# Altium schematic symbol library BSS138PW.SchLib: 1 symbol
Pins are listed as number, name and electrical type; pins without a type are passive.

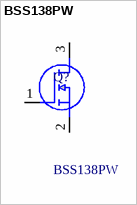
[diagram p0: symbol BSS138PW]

## BSS138PW
designator Q?
MOSFET,n-channel,60V,320mA,0.9ohm,SOT323 NXP BSS138PW N-channel MOSFET Transistor, 320 mA, 60 V, 3-Pin SOT-323; Manufacturer_Name: Nexperia; Geometry.Height: 1.1mm
footprint SOT65P210X110-3N
pins: 1 G, 2 S, 3 D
